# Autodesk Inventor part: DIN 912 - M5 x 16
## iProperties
IsCustomPart: 1
Created: 2006-02
Part Number: DIN 912 - M5 x 16
Material: Steel, Mild
Description: Cylinder Head Cap Screw
Document SubType Name: Modeling
Standard: DIN 912
Designer: Andy Moles
Standards Organization: DIN
Language: en-US
Size Designation: M5 x 16
Categories: <MemberInstance><Categories><Category DisplayName="Fasteners" InternalName="e4da775c-781d-43d5-af7c-5136215cf5a6" Mnemonic="FSTN"><Category DisplayName="Bolts"
Density: 1 g/cm^3
Author: Andy Moles
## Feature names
1. Body [Revolution]
2. Slot [Extrusion]
3. Fillet1
4. Chamfer1
